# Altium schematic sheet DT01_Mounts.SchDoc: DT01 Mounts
size A4; DocumentNumber: 3; SheetNumber: 3; SheetTotal: 12
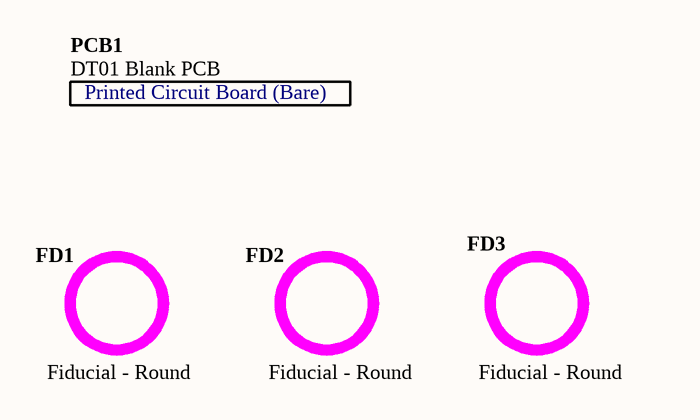
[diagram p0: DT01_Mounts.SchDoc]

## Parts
FD1  Fiducial - Round  [FIDUCIAL 2]
FD2  Fiducial - Round  [FIDUCIAL 2]
FD3  Fiducial - Round  [FIDUCIAL 2]
PCB1  DT01 Blank PCB

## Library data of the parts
FD1-FD3 = D-004-0001: Fiducial - Round 1.5mm Top-Bottom
PCB1 = D-810-0014: DT01 Blank PCB - USB JTAG Adaptor with SD Card and 1-Wire; ProjectPath: DT01.PrjPCB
